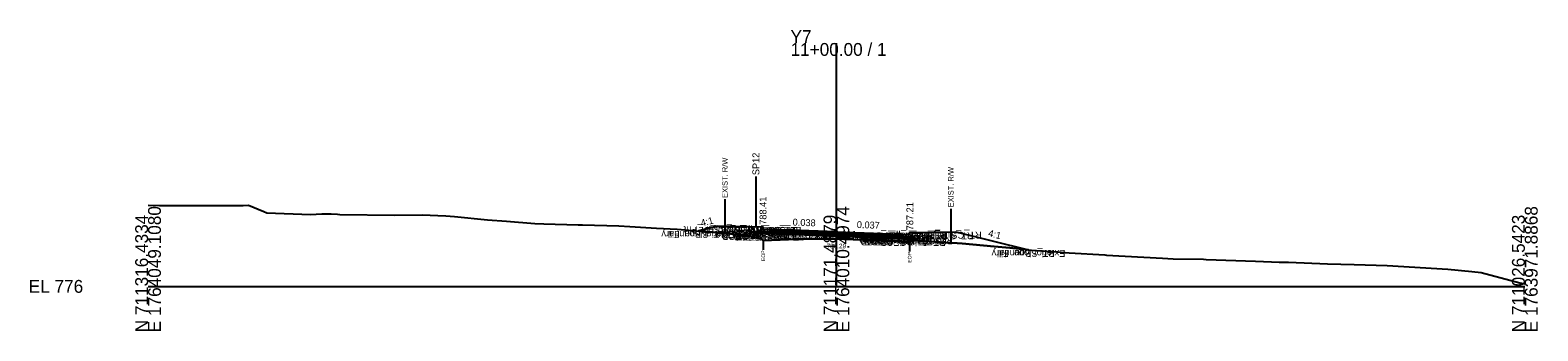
# Model space of a CAD drawing. Extents: x -26 to 2903, y -10 to 1056.
# Drawn here: x -25.7 to 302.8, y 990.3 to 1055.8 of the extents above; entities that cross this region are included whole.
import ezdxf

# ---------------------------------------------------------------- set-up
doc = ezdxf.new("R2010")
doc.units = 0
for name, color, linetype in [('Default', 7, 'Continuous'), ('Exist Cross Section Cell', 7, 'Continuous'), ('Exist XS Center Line Elevation Label', 7, 'Continuous'), ('Exist XS Ground Line', 7, 'Continuous'), ('Old_Level_10', 7, 'Continuous'), ('Prop CMT Conc Surface', 7, 'Continuous'), ('Prop CMT Concrete Structures', 7, 'Continuous'), ('Prop CMT Pvmt Course 1', 7, 'Continuous'), ('Prop CMT Pvmt Course 1 CG', 7, 'Continuous'), ('Prop CMT Pvmt Course 2', 7, 'Continuous'), ('Prop CMT Pvmt Course 3', 7, 'Continuous'), ('Prop CMT Pvmt Surface', 7, 'Continuous'), ('Prop CMT Slope Grass', 7, 'Continuous'), ('Prop CMT Subgrade Earthwork', 7, 'Continuous'), ('Prop XS Earthwork Shape', 7, 'Continuous'), ('Prop XS Hydro Elevations', 7, 'Continuous'), ('Prop XS SE Text', 7, 'Continuous'), ('Prop XS Shear Point Element', 7, 'Continuous'), ('Prop XS Side Slope Text', 7, 'Continuous'), ('Scratch_Level_7', 7, 'Continuous')]:
    doc.layers.add(name, color=color, linetype=linetype)

msp = doc.modelspace()

# ---------------------------------------------------------------- linework, layer by layer
at = {"layer": 'Exist Cross Section Cell'}
for p, q in [((150, 1000), (150, 1053.02)), ((0, 1000), (150, 1000)), ((150, 1000), (300, 1000))]:
    msp.add_line(p, q, dxfattribs=at)
at = {"layer": 'Exist XS Ground Line'}
msp.add_lwpolyline([(0, 1017.67), (2.47, 1017.58), (3.15, 1017.58), (20.75, 1017.64), (21.85, 1017.66), (25.22, 1016.28), (25.88, 1016.03), (35.4, 1015.64), (37.83, 1015.8), (39.93, 1015.78), (41.29, 1015.72), (41.76, 1015.69), (53.74, 1015.53), (59.71, 1015.55), (64.92, 1015.34), (66.75, 1015.19), (73.93, 1014.46), (78.09, 1014.23), (84.28, 1013.73), (86.26, 1013.65), (93.71, 1013.4), (94.63, 1013.37), (102.61, 1013.18), (104.98, 1013.01), (110.78, 1012.7), (115.33, 1012.49), (126.28, 1011.5), (128.94, 1011.23), (129.35, 1011.2), (133.52, 1010.46), (134.05, 1009.99), (139.56, 1010.24), (140.82, 1010.28), (142.48, 1010.31), (143.45, 1010.32), (145.07, 1010.35), (145.49, 1010.35), (147.08, 1010.34), (147.66, 1010.34), (148.56, 1010.33), (149.82, 1010.28), (150.55, 1010.32), (151.62, 1010.3), (152.83, 1010.27), (153.67, 1010.24), (155.71, 1010.17), (156.79, 1010.14), (158.01, 1010.1), (159.79, 1010.03), (160.59, 1010), (161.84, 1009.92), (163.18, 1009.84), (163.88, 1009.79), (165.25, 1009.66), (165.95, 1009.61), (166.57, 1010.01), (176.34, 1009.43), (177.43, 1009.34), (184.34, 1008.7), (187.78, 1008.36), (192.51, 1007.86), (198.13, 1007.53), (200.69, 1007.33), (208.48, 1006.85), (208.86, 1006.83), (221.02, 1006.12), (223.41, 1005.99), (230.01, 1005.9), (230.56, 1005.87), (241.35, 1005.48), (244.82, 1005.36), (246.49, 1005.3), (246.84, 1005.29), (247.26, 1005.29), (248.52, 1005.24), (256.99, 1004.91), (262.81, 1004.73), (270.03, 1004.51), (283.26, 1003.77), (288.43, 1003.25), (290.51, 1003.03), (298.95, 1000.78), (300, 1000.56)], dxfattribs=at)
at = {"layer": 'Old_Level_10'}
for p, q in [((125.7, 1018.96), (125.7, 1011.55)), ((174.93, 1016.92), (174.93, 1009.52)), ((134.05, 1009.99), (134.05, 1007.94)), ((165.95, 1009.61), (165.95, 1007.56))]:
    msp.add_line(p, q, dxfattribs=at)
at = {"layer": 'Prop CMT Conc Surface'}
for points in [[(134, 1012.41), (134, 1012.91), (133.5, 1012.91)], [(136, 1012.41), (134, 1012.41)], [(164, 1011.36), (166, 1011.21)], [(166, 1011.21), (166, 1011.71), (166.5, 1011.71)]]:
    msp.add_lwpolyline(points, dxfattribs=at)
at = {"layer": 'Prop CMT Concrete Structures'}
for points in [[(136, 1012.41), (134, 1012.41), (134, 1012.91), (133.5, 1012.91)], [(133.5, 1012.91), (133.5, 1011.92), (136, 1011.83)], [(136, 1011.83), (136, 1012.41)], [(164, 1011.36), (166, 1011.21), (166, 1011.71), (166.5, 1011.71)], [(166.5, 1011.71), (166.5, 1010.69), (164, 1010.78)], [(164, 1010.78), (164, 1011.36)]]:
    msp.add_lwpolyline(points, dxfattribs=at)
at = {"layer": 'Prop CMT Pvmt Course 1'}
for points in [[(150, 1011.89), (136, 1012.41)], [(136, 1012.41), (136, 1012.16)], [(136, 1012.16), (136.05, 1012.16)], [(136.05, 1012.16), (150, 1011.64)], [(150, 1011.64), (150, 1011.89)], [(150, 1011.89), (164, 1011.36)], [(150, 1011.64), (150, 1011.64)], [(150, 1011.64), (150, 1011.64), (150, 1011.64)], [(163.95, 1011.11), (150, 1011.64)], [(164, 1011.11), (163.95, 1011.11)], [(164, 1011.36), (164, 1011.11)]]:
    msp.add_lwpolyline(points, dxfattribs=at)
at = {"layer": 'Prop CMT Pvmt Course 1 CG'}
for points in [[(136, 1011.83), (133, 1011.94), (132.68, 1011.62)], [(132.68, 1011.62), (136, 1011.5)], [(136, 1011.5), (136, 1011.83)], [(164, 1010.78), (167, 1010.67), (167.35, 1010.32)], [(164, 1010.45), (164, 1010.78)], [(167.35, 1010.32), (164, 1010.45)]]:
    msp.add_lwpolyline(points, dxfattribs=at)
at = {"layer": 'Prop CMT Pvmt Course 2'}
for p in [(136, 1011.83), (164, 1010.78)]:
    msp.add_line(p, (150, 1011.3), dxfattribs=at)
for points in [[(136.05, 1012.16), (136, 1012.16)], [(136, 1012.16), (136, 1011.83)], [(150, 1011.3), (150, 1011.64)], [(163.95, 1011.11), (164, 1011.11)], [(164, 1011.11), (164, 1010.78)]]:
    msp.add_lwpolyline(points, dxfattribs=at)
at = {"layer": 'Prop CMT Pvmt Course 3'}
for p, q in [((150, 1011.3), (136, 1011.83)), ((136, 1011.5), (150, 1010.97)), ((150, 1011.3), (164, 1010.78)), ((164, 1010.45), (150, 1010.97))]:
    msp.add_line(p, q, dxfattribs=at)
for points in [[(136, 1011.83), (136, 1011.5)], [(150, 1010.97), (150, 1011.3)], [(164, 1010.78), (164, 1010.45)]]:
    msp.add_lwpolyline(points, dxfattribs=at)
at = {"layer": 'Prop CMT Pvmt Surface'}
for points in [[(150, 1011.89), (136, 1012.41)], [(150, 1011.89), (164, 1011.36)]]:
    msp.add_lwpolyline(points, dxfattribs=at)
at = {"layer": 'Prop CMT Slope Grass'}
for points in [[(133.5, 1012.91), (124, 1013.1), (119.91, 1012.08)], [(166.5, 1011.71), (176, 1011.9), (191.87, 1007.93)]]:
    msp.add_lwpolyline(points, dxfattribs=at)
at = {"layer": 'Prop CMT Subgrade Earthwork'}
for q in [(136, 1011.5), (164, 1010.45)]:
    msp.add_line((150, 1010.97), q, dxfattribs=at)
for points in [[(136, 1011.5), (132.68, 1011.62), (131.35, 1012.95)], [(164, 1010.45), (167.35, 1010.32), (168.78, 1011.75)]]:
    msp.add_lwpolyline(points, dxfattribs=at)
at = {"layer": 'Prop XS Earthwork Shape'}
msp.add_lwpolyline([(164, 1010.45), (167.35, 1010.32), (168.78, 1011.75), (176, 1011.9), (191.87, 1007.93), (187.78, 1008.36), (184.34, 1008.7), (177.43, 1009.34), (176.34, 1009.43), (166.57, 1010.01), (165.95, 1009.61), (165.25, 1009.66), (163.88, 1009.79), (163.18, 1009.84), (161.84, 1009.92), (160.59, 1010), (159.79, 1010.03), (158.01, 1010.1), (156.79, 1010.14), (155.71, 1010.17), (153.67, 1010.24), (152.83, 1010.27), (151.62, 1010.3), (150.55, 1010.32), (149.82, 1010.28), (148.56, 1010.33), (147.66, 1010.34), (147.08, 1010.34), (145.49, 1010.35), (145.07, 1010.35), (143.45, 1010.32), (142.48, 1010.31), (140.82, 1010.28), (139.56, 1010.24), (134.05, 1009.99), (133.52, 1010.46), (129.35, 1011.2), (128.94, 1011.23), (126.28, 1011.5), (119.91, 1012.08), (124, 1013.1), (131.35, 1012.95), (132.68, 1011.62), (136, 1011.5), (150, 1010.97)], close=True, dxfattribs=at)
at = {"layer": 'Prop XS Shear Point Element'}
msp.add_line((132.52, 1012.93), (132.52, 1023.95), dxfattribs=at)

# ---------------------------------------------------------------- texts
at = {"layer": 'Default'}
msp.add_text('-', height=0.0001, dxfattribs=at).set_placement((0, 1000))
at = {"layer": 'Exist Cross Section Cell'}
for s, p in [('Y7', (140, 1053.02)), ('11+00.00 / 1', (140, 1050.22)), ('EL 776', (-26, 998.6))]:
    msp.add_text(s, height=2.8, dxfattribs=at).set_placement(p)
for s, p in [('N 711316.4334', (0, 990)), ('E 1764049.1080', (2.8, 990)), ('N 711171.4879', (150, 990)), ('E 1764010.4974', (152.8, 990)), ('N 711026.5423', (300, 990)), ('E 1763971.8868', (302.8, 990))]:
    msp.add_text(s, height=2.8, rotation=90, dxfattribs=at).set_placement(p)
at = {"layer": 'Exist XS Center Line Elevation Label'}
msp.add_text('786.29', height=1, dxfattribs=at).set_placement((147.87, 1008.29))
at = {"layer": 'Old_Level_10'}
for s, height, p in [('EXIST. R/W', 1.181, (126.29, 1019.26)), ('EXIST. R/W', 1.181, (175.52, 1017.22)), ('EOP', 0.787, (134.44, 1005.54)), ('EOP', 0.787, (166.35, 1005.17))]:
    msp.add_text(s, height=height, rotation=90, dxfattribs=at).set_placement(p)
at = {"layer": 'Prop XS Hydro Elevations'}
for s, p in [('788.41', (134.75, 1013.41)), ('787.21', (166.75, 1012.21))]:
    msp.add_text(s, height=1.5, rotation=90, dxfattribs=at).set_placement(p)
at = {"layer": 'Prop XS SE Text'}
for s, p in [('0.038', (140.43, 1013.25)), ('0.037', (154.41, 1012.72))]:
    msp.add_text(s, height=1.5, rotation=357.8524, dxfattribs=at).set_placement(p)
at = {"layer": 'Prop XS Shear Point Element'}
msp.add_text('SP12', height=1.5, rotation=90, dxfattribs=at).set_placement((133.2, 1024.22))
at = {"layer": 'Prop XS Side Slope Text'}
for rotation, p in [(14.0362, (120.62, 1013.03)), (345.9638, (182.96, 1010.93))]:
    msp.add_text('4:1', height=1.5, rotation=rotation, dxfattribs=at).set_placement(p)
at = {"layer": 'Scratch_Level_7'}
for s, p in [('Exterior Boundary', (127.92, 1012.08)), ('LT_Slope_Fill', (125.55, 1012.08)), ('LT_CSLP_Pnt', (129.55, 1013.1)), ('LT_Sub_Trench_Out_DLT', (142.37, 1012.95)), ('LT_CG1_Shelf_Out', (141.27, 1011.94)), ('LT_CG_Top_BOC', (141.14, 1012.91)), ('LT_CG_Bot_BOC', (140.93, 1011.92)), ('LT_CG_Top_Face', (141.62, 1012.91)), ('LT_Sub_OEOP', (139.03, 1011.62)), ('LT_CG_Top_Gut', (141.22, 1012.41)), ('LT_PV1_OEEOP', (142.78, 1012.16)), ('LT_PV2_OEEOP', (142.96, 1012.16)), ('LT_PV3_OEEOP', (142.96, 1011.83)), ('LT_Sub_OEEOP', (142.93, 1011.49)), ('LT_PV1_OEOT', (142.2, 1012.41)), ('LT_PV2_OEOT', (142.38, 1012.16)), ('LT_PV3_OEOT', (142.38, 1011.83)), ('LT_Sub_OEOT', (142.35, 1011.5)), ('LT_CG_Bot_IE', (142.12, 1011.83)), ('RT_PV1_IEEOP', (156.25, 1011.64)), ('RT_PV2_IEEOP', (156.43, 1011.64)), ('LT_PV1_IEEOP', (156.16, 1011.64)), ('LT_PV2_IEEOP', (156.34, 1011.64)), ('PV1_PGL', (153.8, 1011.89)), ('PV2_PGL', (153.97, 1011.64)), ('RT_Sub_Trench_Out_DLT', (179.89, 1011.75)), ('RT_CG_Top_Face', (173.71, 1011.71)), ('RT_CG_Top_BOC', (174.23, 1011.71)), ('RT_CSLP_Pnt', (181.64, 1011.9)), ('RT_PV1_OEEOP', (170.77, 1011.11)), ('RT_PV2_OEEOP', (170.95, 1011.11)), ('RT_PV3_OEEOP', (170.95, 1010.78)), ('RT_Sub_OEEOP', (170.92, 1010.45)), ('RT_PV1_OEOT', (170.29, 1011.36)), ('RT_PV2_OEOT', (170.47, 1011.11)), ('RT_PV3_OEOT', (170.47, 1010.78)), ('RT_Sub_OEOT', (170.44, 1010.45)), ('RT_CG_Bot_IE', (170.21, 1010.78)), ('RT_CG1_Shelf_Out', (175.36, 1010.67)), ('RT_CG_Top_Gut', (173.31, 1011.21)), ('RT_CG_Bot_BOC', (174.02, 1010.69)), ('RT_Sub_OEOP', (173.79, 1010.32)), ('Exterior Boundary', (199.88, 1007.93)), ('RT_Slope_Fill', (197.6, 1007.93))]:
    msp.add_text(s, height=1.5, rotation=180, dxfattribs=at).set_placement(p)

doc.saveas('drawing.dxf')
